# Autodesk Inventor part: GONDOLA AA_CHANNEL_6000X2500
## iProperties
Shininess: 64.0
Length Units: 11272
Angle Units: 11279
Time Units: 11290
Mass Units: 11286
Length Display Precision: 3
Angle Display Precision: 2
Compacted: True
Part Number: GONDOLA AA_CHANNEL_6000X2500
Document SubType Name: Modeling
Created: 2004-08
Designer: John Blackburn
Manufacturer: Standard
Standards Organization: Custom
Density: 0.0
Volumn: 0.0
Area: 0.0
PropertySet Name: Model Information
Control State: 0
Master: False
Checked Out: False
Author: John Blackburn
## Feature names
1. ExtrusionMidplane1
2. ExtrusionThru1
3. AM_HOLE_0301DE_1 [Hole]
4. AM_HOLE_UTHRGH_1 [Hole]
5. Hole1
6. Hole2
7. Hole3
